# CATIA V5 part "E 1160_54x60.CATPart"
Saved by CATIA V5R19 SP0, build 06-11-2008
Definition: E 1160_54x60
Nomenclature: E 1160_54x60
Description: PART--DESC
Material "Steel": density 7860 kg/m3, Young's modulus 2e+11 Pa, Poisson ratio 0.266, thermal expansion 1.17e-05 1/K
Bounding box of the stored display mesh (mm): x 252 to 306, y 202 to 256, z 80 to 140
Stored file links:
  G:\UTB\Kombinované\Bakalářská práce\Catia\FORMA\E 1160_54x60.CATPart
  D:\Aplikace\CATIA\Nová složka\win_b64\startup\materials\Catalog.CATMaterial
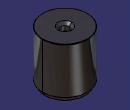
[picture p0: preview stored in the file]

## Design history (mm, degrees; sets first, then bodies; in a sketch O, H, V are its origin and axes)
Body1 "E 1160_54x60" (main body)
  Solid1: solid without history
